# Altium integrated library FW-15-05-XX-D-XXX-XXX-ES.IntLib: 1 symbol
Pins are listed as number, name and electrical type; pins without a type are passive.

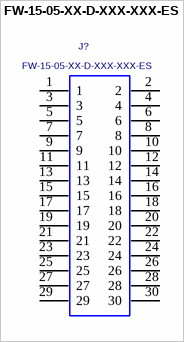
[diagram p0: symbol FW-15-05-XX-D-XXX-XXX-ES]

## FW-15-05-XX-D-XXX-XXX-ES
designator J?
0.05" PITCH SURFACE MOUNT BOARD SPACERS. 30PINS.; MANUFACTURER: SAMTEC
footprint FW-15-05-XX-D-XXX-XXX-ES
pins: 1, 2, 3, 4, 5, 6, 7, 8, 9, 10, 11, 12, 13, 14, 15, 16, 17, 18, 19, 20, 21, 22, 23, 24, 25, 26, 27, 28, 29, 30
